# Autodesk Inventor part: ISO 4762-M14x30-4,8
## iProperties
Shininess: 64.0
Length Units: 11269
Angle Units: 11279
Time Units: 11290
Mass Units: 11283
Length Display Precision: 3
Angle Display Precision: 2
Compacted: True
Part Number: ISO 4762-M14x30-4,8
Document SubType Name: Modeling
Created: 2005-02
Material: Par défaut
Designer: LEGERET Philippe
Catalog Web Link: www.traceparts.com
Description: Vis à métaux - Tête cylindrique à 6 pans creux, ISO 4762-M14x30-4,8
Density: 0.0
Volumn: 0.0
Area: 0.0
PropertySet Name: Model Information
Control State: 0
Master: False
Checked Out: False
Author: Trace Parts S.A.
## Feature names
1. Base1
